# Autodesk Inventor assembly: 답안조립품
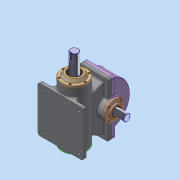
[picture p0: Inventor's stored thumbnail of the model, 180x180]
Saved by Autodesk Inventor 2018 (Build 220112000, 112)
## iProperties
Created: 2023-07
Part Number: 답안조립품
Material: 일반
Document SubType Name: Assembly
Designer: home
Author: home
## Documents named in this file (14)
- C:\Users\home\Desktop\730706V1018\답안조립품.iam
- C:\Users\home\Desktop\730706V1018\본체.ipt
- C:\Users\home\Desktop\730706V1018\깊은 홈 볼 베어링 6209.ipt
- C:\Users\home\Desktop\730706V1018\웜 샤프트.ipt
- C:\Users\home\Desktop\730706V1018\앞커버.ipt
- C:\Users\home\Desktop\730706V1018\뒤커버.ipt
- C:\Users\home\Desktop\730706V1018\육각 소켓 머리 볼트 M5 x 12.ipt
- C:\Users\home\Desktop\730706V1018\오일 실 35 55 11.ipt
- C:\Users\home\Desktop\730706V1018\깊은 홈 볼 베어링 6206.ipt
- C:\Users\home\Desktop\730706V1018\웜 휠.ipt
- C:\Users\home\Desktop\730706V1018\본체 커버.ipt
- C:\Users\home\Desktop\730706V1018\육각 소켓 머리 볼트 M6 x 20.ipt
- C:\Users\home\Desktop\730706V1018\서브커버.ipt
- C:\Users\home\Desktop\730706V1018\오일 실 30 42 7.ipt
